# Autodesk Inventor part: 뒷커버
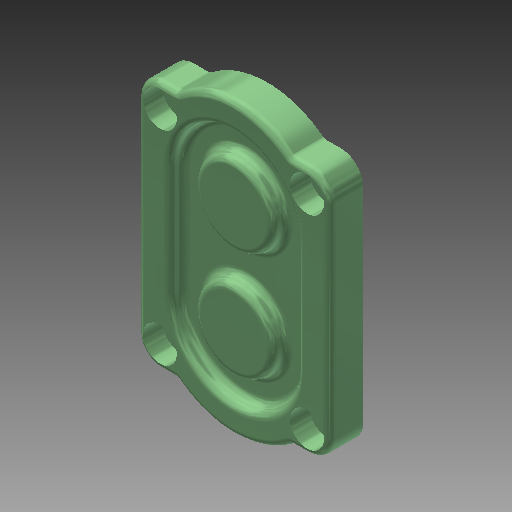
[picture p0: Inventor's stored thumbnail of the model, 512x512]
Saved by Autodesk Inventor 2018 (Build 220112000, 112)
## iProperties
Created: 2013-07
Part Number: 뒷커버
Document SubType Name: Modeling
Designer: 한국산업디자인학원
Density: 1 g/cm^3
Mass: 127.306 g
Surface Area: 321.226 cm^2
Volume: 127.306 cm^3
Material: 알루미늄 6061
Appearance: 알루미늄 - 평지(1)
Author: 한국산업디자인학원
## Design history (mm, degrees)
sketch "스케치1"
  geometry: L1 (-28.5, -82.106)-(-28.5, -34.106) reference; L2 (28.5, -34.106)-(28.5, -82.106) reference; L3 (-42.5, -103.106)-(-42.5, -13.106) reference; L4 (-26.325, -113.106)-(-32.5, -113.106) reference; L5 (32.5, -113.106)-(26.325, -113.106) reference; L6 (42.5, -13.106)-(42.5, -103.106) reference; L7 (26.325, -3.106)-(32.5, -3.106) reference; L8 (-32.5, -3.106)-(-26.325, -3.106) reference; C1 r 4.5 at (-32.5, -13.106) reference; C2 r 4.5 at (32.5, -103.106) reference; C3 r 4.5 at (-32.5, -103.106) reference; C4 r 4.5 at (32.5, -13.106) reference; A1 r 28.5 centre (0, -82.106) between (-28.5, -82.106) and (28.5, -82.106) reference; A2 r 28.5 centre (0, -34.106) between (28.5, -34.106) and (-28.5, -34.106) reference; A3 r 10 centre (-32.5, -103.106) between (-42.5, -103.106) and (-32.5, -113.106) reference; A4 r 3 centre (-26.325, -116.106) between (-24.488, -113.734) and (-26.325, -113.106) reference; A5 r 40 centre (0, -82.106) between (-24.488, -113.734) and (24.488, -113.734) reference; A6 r 3 centre (26.325, -116.106) between (26.325, -113.106) and (24.488, -113.734) reference; A7 r 10 centre (32.5, -103.106) between (32.5, -113.106) and (42.5, -103.106) reference; A8 r 10 centre (32.5, -13.106) between (42.5, -13.106) and (32.5, -3.106) reference; A9 r 3 centre (26.325, -0.106) between (24.488, -2.478) and (26.325, -3.106) reference; A10 r 40 centre (0, -34.106) between (24.488, -2.478) and (-24.488, -2.478) reference; A11 r 3 centre (-26.325, -0.106) between (-26.325, -3.106) and (-24.488, -2.478) reference; A12 r 10 centre (-32.5, -13.106) between (-32.5, -3.106) and (-42.5, -13.106) reference
extrude "돌출1" new body sketch "스케치1" distance "d0" = 15; taper "d1" = 0 deg
sketch "스케치2"
  geometry: L1 (-28.5, -34.106)-(-28.5, -82.106) reference; L2 (28.5, -82.106)-(28.5, -34.106) reference; A1 r 28.5 centre (0, -34.106) between (28.5, -34.106) and (-28.5, -34.106) reference; A2 r 28.5 centre (0, -82.106) between (-28.5, -82.106) and (28.5, -82.106) reference
extrude "돌출2" join sketch "스케치2" distance "d2" = 5; taper "d3" = 0 deg
sketch "스케치11"
  geometry: L1 (-103.106, 15)-(-13.106, 15) reference; L2 (-82.106, -5)-(-110.606, -5) reference; L3 (-82.106, -5)-(-82.106, 15); L4 (-96.106, -5)-(-96.106, 8); L5 (-96.106, 8)-(-92.106, 8); L6 (-90.106, 10)-(-82.106, 10); A1 r 2 centre (-90.106, 8) between (-90.106, 10) and (-92.106, 8); 1 further point
  constraints: 8 end point, 4 point on line, 2 parallel, 2 perpendicular, 2 point on circle, 1 centre point, 1 tangent, 1 vertical alignment
  dimensions: "d77" = 13 distance of L4.start L4.end; "d78" = 2 distance between parallel lines of L6 L5; "d79" = 28 diameter of L4 L3; "d80" = 20 diameter of L5.end L3
revolve "회전1" sketch "스케치11" stored, may be unused: angle "d81" = 90 deg
sketch "스케치8"
  geometry: L1 (28, -82.106)-(28, -34.106); L2 (-28, -82.106)-(-28, -34.106); C1 r 17.5 at (0, -82.106); C2 r 17.5 at (0, -34.106); A1 r 28 centre (0, -82.106) between (28, -82.106) and (-28, -82.106); A2 r 28 centre (0, -34.106) between (-17.161, -56.231) and (17.161, -56.231); A3 r 40 centre (0, -34.106) between (24.488, -2.478) and (-24.488, -2.478) reference; A4 r 40 centre (0, -82.106) between (-24.488, -113.734) and (24.488, -113.734) reference
  constraints: 6 point on circle, 4 centre point, 4 end point, 3 concentric, 2 equal radius, 2 parallel, 1 coincident, 1 tangent, 1 vertical
  dimensions: "d43" = 56 diameter of A1; "d44" = 35 diameter of C1
extrude "돌출5" cut sketch "스케치8" distance "d47" = 6; taper "d48" = 0 deg
fillet "모깎기1" dims "d49" = 3
fillet "모깎기2" dims "d50" = 3, "d51" = 0.3
chamfer "모따기1" distance "d52" = 1; stored, may be unused: second distance "d53" = 2, angle "d54" = 45 deg
sketch "스케치9"
  geometry: C1 r 4.5 at (-32.5, -13.106) reference; C2 r 4.5 at (32.5, -13.106) reference; C3 r 4.5 at (32.5, -103.106) reference; C4 r 4.5 at (-32.5, -103.106) reference; 1 further point
hole "구멍5" sketch "스케치9" at (-32.5, -13.106), (32.5, -13.106), (-32.5, -103.106), (32.5, -103.106) diameter "d55" = 9; stored, may be unused: countersink angle "d59" = 90 deg, drill point angle "d61" = 118 deg; dims "d56" = 6, "d57" = 15, "d58" = 8.8, "d60" = 8
node "솔리드1"
pattern_linear "직사각형 패턴1" dims "d84" = 48
node "참조10"
node "참조11"
node "참조12"
node "참조13"
node "참조14"
node "참조15"
node "참조16"
node "참조17"
node "참조18"
